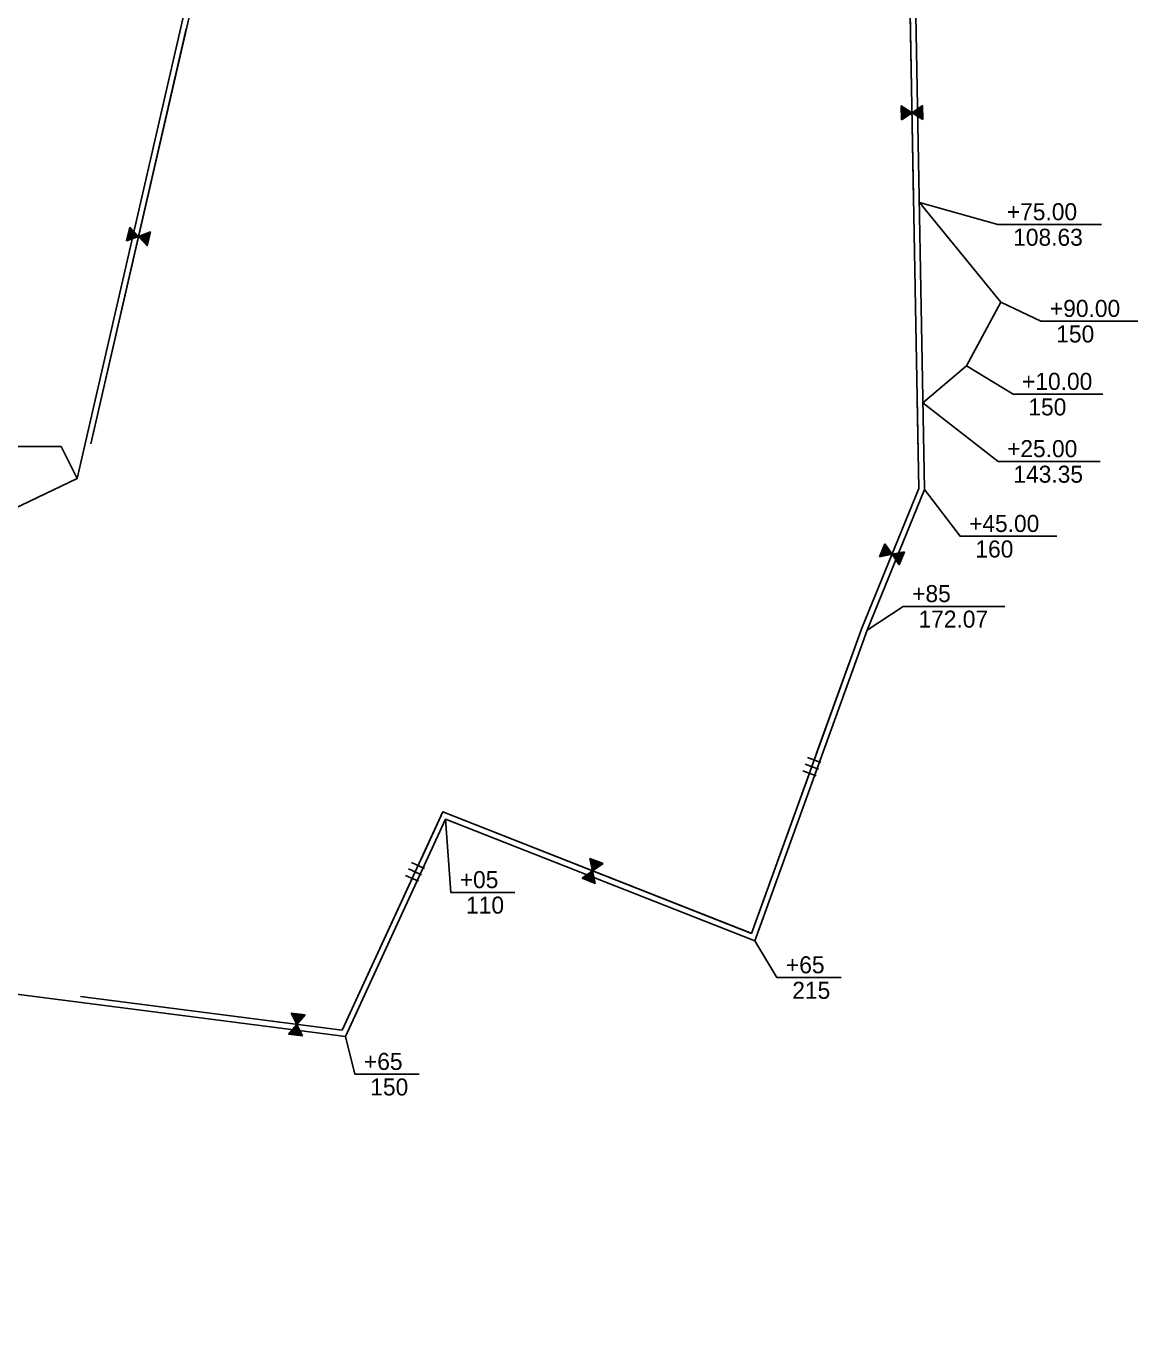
# Model space of a CAD drawing. Extents: x 979729 to 993523, y 1834148 to 1845433.
# Drawn here: x 982395.4 to 982787.1, y 1841740.7 to 1842204.6 of the extents above; entities that cross this region are included whole.
import ezdxf

# ---------------------------------------------------------------- set-up
doc = ezdxf.new("R2010")
doc.units = 0
for name, color, linetype in [('42', 7, 'Continuous'), ('51', 7, 'Continuous'), ('53', 7, 'Continuous'), ('R_Draft', 7, 'Continuous')]:
    doc.layers.add(name, color=color, linetype=linetype)

msp = doc.modelspace()

# ---------------------------------------------------------------- linework, layer by layer
at = {"layer": '42'}
for p, q in [((982710.03, 1842041.79), (982706.26, 1842249.17)), ((982454.62, 1842215.89), (982418.19, 1842057.48)), ((982433.1, 1842129.92), (982431.41, 1842131.71)), ((982433.38, 1842129.98), (982431.48, 1842132)), ((982433.6, 1842130.11), (982431.55, 1842132.29)), ((982433.89, 1842130.17), (982431.61, 1842132.58)), ((982434.13, 1842130.29), (982431.68, 1842132.88)), ((982434.39, 1842130.37), (982431.75, 1842133.17)), ((982434.61, 1842130.5), (982431.82, 1842133.46)), ((982434.9, 1842130.56), (982431.88, 1842133.75)), ((982435, 1842130.57), (982431.91, 1842133.85)), ((982435, 1842130.57), (982439.21, 1842132.17)), ((982435.08, 1842130.52), (982439.19, 1842132.07)), ((982435.31, 1842130.34), (982439.12, 1842131.78)), ((982430.78, 1842128.98), (982435, 1842130.57)), ((982430.85, 1842129.02), (982430.81, 1842129.07)), ((982431.09, 1842129.13), (982430.87, 1842129.36)), ((982431.36, 1842129.21), (982430.94, 1842129.66)), ((982431.6, 1842129.33), (982431.01, 1842129.95)), ((982431.86, 1842129.41), (982431.07, 1842130.24)), ((982432.13, 1842129.49), (982431.14, 1842130.53)), ((982432.37, 1842129.6), (982431.21, 1842130.83)), ((982432.86, 1842129.81), (982431.34, 1842131.41)), ((982432.56, 1842129.76), (982431.39, 1842131)), ((982438.09, 1842127.3), (982435, 1842130.57)), ((982435.45, 1842130.12), (982439.06, 1842131.49)), ((982435.66, 1842129.93), (982438.99, 1842131.2)), ((982435.82, 1842129.73), (982438.92, 1842130.9)), ((982436.05, 1842129.55), (982438.86, 1842130.61)), ((982436.2, 1842129.34), (982438.79, 1842130.32)), ((982436.43, 1842129.16), (982438.72, 1842130.02)), ((982436.59, 1842128.95), (982438.65, 1842129.73)), ((982436.83, 1842128.77), (982438.43, 1842129.38)), ((982436.94, 1842128.55), (982438.52, 1842129.15)), ((982437.11, 1842128.34), (982438.45, 1842128.85)), ((982437.31, 1842128.15), (982438.38, 1842128.56)), ((982437.52, 1842127.96), (982438.32, 1842128.27)), ((982437.68, 1842127.76), (982438.25, 1842127.97)), ((982437.89, 1842127.57), (982438.18, 1842127.68)), ((982438.05, 1842127.37), (982438.11, 1842127.39)), ((982689.97, 1841992.55), (982710.03, 1842041.79)), ((982650.99, 1841884.98), (982689.97, 1841992.55)), ((982535.78, 1841907.86), (982531.24, 1841909.96)), ((982595, 1841907), (982594.05, 1841911.41)), ((982595.07, 1841907.08), (982594.14, 1841911.37)), ((982595.28, 1841907.28), (982594.42, 1841911.26)), ((982595.52, 1841907.38), (982594.7, 1841911.15)), ((982595.73, 1841907.56), (982594.98, 1841911.04)), ((982598.7, 1841909.58), (982595, 1841907)), ((982595.96, 1841907.69), (982595.26, 1841910.93)), ((982596.17, 1841907.9), (982595.54, 1841910.82)), ((982596.4, 1841908), (982595.82, 1841910.71)), ((982596.62, 1841908.2), (982596.1, 1841910.6)), ((982596.84, 1841908.34), (982596.38, 1841910.49)), ((982597.05, 1841908.55), (982596.69, 1841910.22)), ((982597.29, 1841908.62), (982596.94, 1841910.27)), ((982597.52, 1841908.76), (982597.22, 1841910.16)), ((982597.74, 1841908.93), (982597.5, 1841910.05)), ((982597.96, 1841909.11), (982597.77, 1841909.94)), ((982598.18, 1841909.24), (982598.05, 1841909.83)), ((982598.4, 1841909.41), (982598.33, 1841909.72)), ((982598.63, 1841909.55), (982598.61, 1841909.61)), ((982533.68, 1841903.32), (982529.14, 1841905.42)), ((982534.73, 1841905.59), (982530.19, 1841907.69)), ((982595, 1841907), (982591.3, 1841904.43)), ((982595, 1841906.9), (982591.4, 1841904.39)), ((982595.02, 1841906.61), (982591.67, 1841904.28)), ((982595.12, 1841906.37), (982591.95, 1841904.17)), ((982595.16, 1841906.1), (982592.23, 1841904.06)), ((982595.23, 1841905.85), (982592.51, 1841903.95)), ((982595.25, 1841905.55), (982592.79, 1841903.84)), ((982595.35, 1841905.32), (982593.07, 1841903.73)), ((982595.37, 1841905.02), (982593.35, 1841903.62)), ((982595.44, 1841904.77), (982593.63, 1841903.51)), ((982595.45, 1841904.47), (982594.05, 1841903.5)), ((982595.96, 1841902.6), (982595, 1841907)), ((982595.58, 1841904.26), (982594.19, 1841903.29)), ((982595.65, 1841904), (982594.47, 1841903.18)), ((982595.69, 1841903.73), (982594.75, 1841903.07)), ((982595.73, 1841903.45), (982595.03, 1841902.96)), ((982595.81, 1841903.2), (982595.31, 1841902.85)), ((982595.85, 1841902.92), (982595.59, 1841902.74)), ((982595.92, 1841902.67), (982595.87, 1841902.63)), ((982490.81, 1841852.87), (982488.81, 1841856.91)), ((982490.86, 1841852.96), (982488.91, 1841856.9)), ((982491.01, 1841853.21), (982489.2, 1841856.86)), ((982491.21, 1841853.37), (982489.5, 1841856.82)), ((982491.38, 1841853.59), (982489.8, 1841856.78)), ((982491.57, 1841853.78), (982490.1, 1841856.75)), ((982491.72, 1841854.02), (982490.39, 1841856.71)), ((982491.92, 1841854.18), (982490.69, 1841856.67)), ((982493.77, 1841856.27), (982490.81, 1841852.87)), ((982492.08, 1841854.43), (982490.99, 1841856.63)), ((982492.27, 1841854.62), (982491.29, 1841856.59)), ((982492.42, 1841854.87), (982491.66, 1841856.4)), ((982492.64, 1841855), (982491.89, 1841856.52)), ((982492.82, 1841855.19), (982492.18, 1841856.48)), ((982492.99, 1841855.41), (982492.48, 1841856.44)), ((982493.16, 1841855.63), (982492.78, 1841856.4)), ((982493.35, 1841855.82), (982493.08, 1841856.36)), ((982493.52, 1841856.04), (982493.37, 1841856.32)), ((982493.7, 1841856.23), (982493.67, 1841856.29)), ((982490.81, 1841852.87), (982487.85, 1841849.47)), ((982490.83, 1841852.78), (982487.95, 1841849.46)), ((982490.92, 1841852.5), (982488.25, 1841849.42)), ((982491.07, 1841852.29), (982488.55, 1841849.38)), ((982491.18, 1841852.03), (982488.84, 1841849.35)), ((982491.31, 1841851.81), (982489.14, 1841849.31)), ((982491.4, 1841851.53), (982489.44, 1841849.27)), ((982491.56, 1841851.32), (982489.74, 1841849.23)), ((982491.64, 1841851.04), (982490.03, 1841849.19)), ((982491.78, 1841850.82), (982490.33, 1841849.15)), ((982491.86, 1841850.53), (982490.74, 1841849.24)), ((982492.81, 1841848.84), (982490.81, 1841852.87)), ((982492.04, 1841850.35), (982490.93, 1841849.08)), ((982492.17, 1841850.12), (982491.23, 1841849.04)), ((982492.28, 1841849.87), (982491.52, 1841849)), ((982492.38, 1841849.61), (982491.82, 1841848.96)), ((982492.52, 1841849.38), (982492.12, 1841848.92)), ((982492.63, 1841849.12), (982492.42, 1841848.89)), ((982492.76, 1841848.9), (982492.72, 1841848.85))]:
    msp.add_line(p, q, dxfattribs=at)
for points in [[(982418.19, 1842057.48), (982451.81, 1842203.67)], [(982430.78, 1842128.98), (982431.91, 1842133.85)], [(982438.09, 1842127.3), (982439.21, 1842132.17)], [(982650.88, 1841885.02), (982542.21, 1841927.77), (982506.71, 1841850.83), (982414.54, 1841862.68)], [(982650.99, 1841884.98), (982542.21, 1841927.77), (982534.56, 1841911.18)], [(982598.7, 1841909.58), (982594.05, 1841911.41)], [(982531.41, 1841904.37), (982506.71, 1841850.83), (982414.54, 1841862.68)], [(982595.96, 1841902.6), (982591.3, 1841904.43)], [(982493.77, 1841856.27), (982488.81, 1841856.91)], [(982492.81, 1841848.84), (982487.85, 1841849.47)]]:
    msp.add_lwpolyline(points, dxfattribs=at)
at = {"layer": '51'}
for p, q in [((982708.26, 1842249.15), (982712.04, 1842041.41)), ((982703.83, 1842176.61), (982707.62, 1842174.18)), ((982703.88, 1842176.55), (982703.83, 1842176.52)), ((982704.09, 1842176.4), (982703.83, 1842176.22)), ((982704.34, 1842176.26), (982703.84, 1842175.92)), ((982704.55, 1842176.1), (982703.84, 1842175.61)), ((982704.79, 1842175.97), (982703.85, 1842175.31)), ((982705.04, 1842175.83), (982703.85, 1842175.01)), ((982705.25, 1842175.68), (982703.86, 1842174.71)), ((982705.68, 1842175.37), (982703.87, 1842174.11)), ((982705.89, 1842175.21), (982703.88, 1842173.81)), ((982706.16, 1842175.09), (982703.88, 1842173.51)), ((982706.35, 1842174.92), (982703.89, 1842173.21)), ((982706.62, 1842174.8), (982703.89, 1842172.91)), ((982706.83, 1842174.64), (982703.9, 1842172.61)), ((982707.07, 1842174.51), (982703.9, 1842172.31)), ((982707.26, 1842174.33), (982703.91, 1842172.01)), ((982707.53, 1842174.21), (982703.91, 1842171.71)), ((982707.62, 1842174.18), (982703.92, 1842171.61)), ((982705.41, 1842175.48), (982704, 1842174.51)), ((982711.32, 1842176.75), (982707.62, 1842174.18)), ((982707.62, 1842174.18), (982711.42, 1842171.75)), ((982707.71, 1842174.22), (982711.41, 1842171.85)), ((982707.98, 1842174.35), (982711.41, 1842172.15)), ((982708.16, 1842174.53), (982711.4, 1842172.45)), ((982708.4, 1842174.67), (982711.4, 1842172.75)), ((982708.6, 1842174.84), (982711.39, 1842173.05)), ((982708.87, 1842174.96), (982711.39, 1842173.35)), ((982709.05, 1842175.14), (982711.38, 1842173.65)), ((982709.31, 1842175.27), (982711.38, 1842173.95)), ((982709.51, 1842175.44), (982711.37, 1842174.25)), ((982709.79, 1842175.56), (982711.22, 1842174.64)), ((982709.94, 1842175.76), (982711.36, 1842174.85)), ((982710.14, 1842175.93), (982711.35, 1842175.15)), ((982710.38, 1842176.07), (982711.35, 1842175.45)), ((982710.62, 1842176.21), (982711.34, 1842175.75)), ((982710.83, 1842176.38), (982711.34, 1842176.05)), ((982711.07, 1842176.52), (982711.33, 1842176.35)), ((982711.27, 1842176.69), (982711.33, 1842176.65)), ((982712.04, 1842041.41), (982691.84, 1841991.84)), ((982699.25, 1842020.41), (982697.09, 1842019.97)), ((982698.97, 1842020.87), (982697.32, 1842020.53)), ((982699.04, 1842020.63), (982697.37, 1842020.28)), ((982698.84, 1842021.09), (982697.43, 1842020.81)), ((982698.67, 1842021.31), (982697.54, 1842021.09)), ((982698.5, 1842021.53), (982697.66, 1842021.36)), ((982698.37, 1842021.76), (982697.77, 1842021.64)), ((982698.19, 1842021.98), (982697.88, 1842021.92)), ((982698.06, 1842022.21), (982698, 1842022.2)), ((982698.03, 1842022.28), (982700.56, 1842018.55)), ((982700.56, 1842018.55), (982696.15, 1842017.65)), ((982700.49, 1842018.62), (982696.18, 1842017.75)), ((982700.29, 1842018.84), (982696.3, 1842018.02)), ((982700.19, 1842019.07), (982696.41, 1842018.3)), ((982700.02, 1842019.29), (982696.52, 1842018.58)), ((982699.88, 1842019.52), (982696.64, 1842018.86)), ((982699.69, 1842019.74), (982696.75, 1842019.14)), ((982699.58, 1842019.97), (982696.86, 1842019.42)), ((982699.38, 1842020.18), (982696.98, 1842019.69)), ((982704.98, 1842019.45), (982700.56, 1842018.55)), ((982700.56, 1842018.55), (982703.09, 1842014.82)), ((982700.66, 1842018.55), (982703.13, 1842014.92)), ((982700.96, 1842018.57), (982703.24, 1842015.19)), ((982701.19, 1842018.66), (982703.36, 1842015.47)), ((982701.47, 1842018.7), (982703.47, 1842015.75)), ((982701.72, 1842018.77), (982703.58, 1842016.03)), ((982702.02, 1842018.79), (982703.7, 1842016.31)), ((982702.25, 1842018.88), (982703.81, 1842016.59)), ((982702.55, 1842018.89), (982703.92, 1842016.86)), ((982702.8, 1842018.97), (982704.04, 1842017.14)), ((982703.1, 1842018.97), (982704.06, 1842017.56)), ((982703.32, 1842019.1), (982704.26, 1842017.7)), ((982703.57, 1842019.17), (982704.38, 1842017.98)), ((982703.85, 1842019.21), (982704.49, 1842018.26)), ((982704.12, 1842019.24), (982704.6, 1842018.53)), ((982704.38, 1842019.31), (982704.72, 1842018.81)), ((982704.65, 1842019.35), (982704.83, 1842019.09)), ((982704.91, 1842019.42), (982704.94, 1842019.37)), ((982691.84, 1841991.84), (982652.17, 1841882.37)), ((982675.48, 1841945.23), (982670.78, 1841946.94)), ((982673.78, 1841940.53), (982669.08, 1841942.24)), ((982674.63, 1841942.88), (982669.93, 1841944.59))]:
    msp.add_line(p, q, dxfattribs=at)
for points in [[(982610.33, 1842460.58), (982522.85, 1842272.24), (982451.95, 1842249.25), (982452.61, 1842216.09), (982413.33, 1842045.26), (982307.06, 1841994.43), (982168.6, 1842021.15)], [(982706.26, 1842249.17), (982708.18, 1842143.5)], [(982703.83, 1842176.61), (982703.92, 1842171.61)], [(982711.32, 1842176.75), (982711.42, 1842171.75)], [(982709.46, 1842073.13), (982710.03, 1842041.79), (982689.97, 1841992.55), (982673.98, 1841948.44)], [(982698.03, 1842022.28), (982696.15, 1842017.65)], [(982704.98, 1842019.45), (982703.09, 1842014.82)], [(982671.43, 1841941.39), (982650.99, 1841884.98)], [(982163.06, 1841753.11), (982303.45, 1841740.75), (982355.37, 1841868.28), (982507.91, 1841848.66), (982543.23, 1841925.22), (982652.17, 1841882.37)]]:
    msp.add_lwpolyline(points, dxfattribs=at)
at = {"layer": '53'}
for p, q in [((982738.92, 1842107.44), (982710.2, 1842142.52)), ((982726.81, 1842085.02), (982738.92, 1842107.44)), ((982726.81, 1842085.02), (982711.48, 1842071.91))]:
    msp.add_line(p, q, dxfattribs=at)
at = {"layer": 'R_Draft'}
for p, q in [((982743.87, 1842134.78), (982774.38, 1842134.78)), ((982759.05, 1842100.71), (982787.15, 1842100.71)), ((982749.22, 1842074.99), (982774.88, 1842074.99)), ((982373.87, 1842056.6), (982401.7, 1842056.6)), ((982743.93, 1842051.29), (982773.88, 1842051.29)), ((982730.54, 1842024.92), (982758.64, 1842024.92)), ((982710.48, 1842000.21), (982740.3, 1842000.21)), ((982551.03, 1841899.43), (982567.67, 1841899.43)), ((982666.01, 1841869.41), (982682.64, 1841869.41)), ((982517.27, 1841835.35), (982533.91, 1841835.35))]:
    msp.add_line(p, q, dxfattribs=at)
for points in [[(982710.2, 1842142.52), (982737.87, 1842134.78), (982743.87, 1842134.78)], [(982738.92, 1842107.44), (982753.05, 1842100.71), (982759.05, 1842100.71)], [(982726.81, 1842085.02), (982743.22, 1842074.99), (982749.22, 1842074.99)], [(982711.48, 1842071.91), (982737.93, 1842051.29), (982743.93, 1842051.29)], [(982413.33, 1842045.26), (982407.7, 1842056.6), (982401.7, 1842056.6)], [(982712.04, 1842041.41), (982724.54, 1842024.92), (982730.54, 1842024.92)], [(982691.84, 1841991.84), (982704.48, 1842000.21), (982710.48, 1842000.21)], [(982543.23, 1841925.22), (982545.03, 1841899.43), (982551.03, 1841899.43)], [(982652.17, 1841882.37), (982660.01, 1841869.41), (982666.01, 1841869.41)], [(982507.91, 1841848.66), (982511.27, 1841835.35), (982517.27, 1841835.35)]]:
    msp.add_lwpolyline(points, dxfattribs=at)

# ---------------------------------------------------------------- texts
for s, p in [('+75.00', (982741.04, 1842136.28)), (' 108.63', (982741.04, 1842127.28)), ('+90.00', (982756.22, 1842102.21)), (' 150', (982756.22, 1842093.21)), ('+10.00', (982746.39, 1842076.49)), (' 150', (982746.39, 1842067.49)), ('+25.00', (982741.11, 1842052.79)), (' 143.35', (982741.11, 1842043.79)), ('+45.00', (982727.72, 1842026.42)), (' 160', (982727.72, 1842017.42)), ('+85', (982707.66, 1842001.71)), (' 172.07', (982707.66, 1841992.71)), ('+05', (982548.21, 1841900.93)), (' 110', (982548.21, 1841891.93)), ('+65', (982663.18, 1841870.91)), (' 215', (982663.18, 1841861.91)), ('+65', (982514.44, 1841836.85)), (' 150', (982514.44, 1841827.85))]:
    msp.add_text(s, height=6, rotation=360, dxfattribs=at).set_placement(p)

doc.saveas('drawing.dxf')
